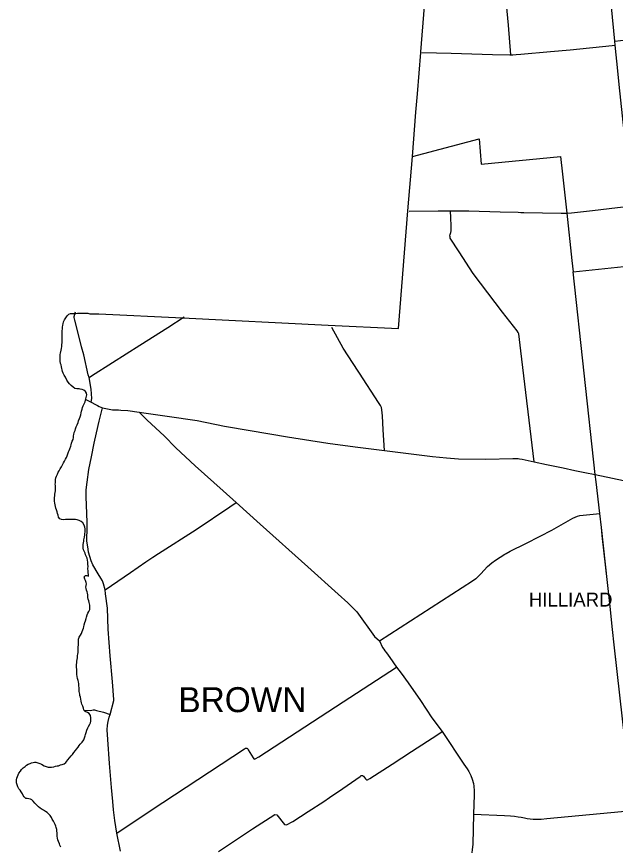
# Model space of a CAD drawing. Extents: x 1755200 to 1902939, y 644115 to 788070.
# Drawn here: x 1755337 to 1776912, y 728043 to 757899 of the extents above; entities that cross this region are included whole.
import ezdxf

# ---------------------------------------------------------------- set-up
doc = ezdxf.new("R2010")
doc.units = 0
for name, color, linetype in [('GM_X_City_Street', 7, 'Continuous'), ('GM_X_Corporation_Text', 7, 'Continuous'), ('GM_X_County', 7, 'Continuous'), ('GM_X_County_Road', 7, 'Continuous'), ('GM_X_Township', 7, 'Continuous'), ('GM_X_Township_Road', 7, 'Continuous'), ('GM_X_Township_Text', 7, 'Continuous')]:
    doc.layers.add(name, color=color, linetype=linetype)

msp = doc.modelspace()

# ---------------------------------------------------------------- linework, layer by layer
at = {"layer": 'GM_X_City_Street'}
for points in [[(1776894, 757007), (1776536, 760730), (1776379, 762498), (1776312, 763238), (1776297, 763289)], [(1773148, 756519), (1773062, 757592), (1772919, 759113), (1772768, 760711), (1772766, 760732)], [(1773219, 756522), (1773341, 756531), (1773503, 756545), (1774575, 756635), (1775276, 756706), (1776795, 756852), (1776906, 756865)], [(1776906, 756865), (1776894, 757007)], [(1777229, 753738), (1777227, 753759), (1777049, 755454), (1776999, 755942), (1776906, 756865)], [(1775031, 741641), (1775451, 741553), (1775814, 741476), (1776185, 741398)], [(1776185, 741398), (1777436, 741136), (1777570, 741122), (1777965, 741145), (1778532, 741169)], [(1776628, 737517), (1776438, 739206)], [(1771881, 737657), (1771905, 737673), (1771965, 737732), (1772058, 737823), (1772302, 738085), (1772460, 738225), (1772594, 738317), (1772932, 738534), (1772978, 738561)], [(1776955, 734518), (1776883, 735163), (1776797, 735932), (1776733, 736538), (1776628, 737517)]]:
    msp.add_lwpolyline(points, dxfattribs=at)
at = {"layer": 'GM_X_County'}
msp.add_lwpolyline([(1756928, 727976), (1756901, 728049), (1756878, 728103), (1756853, 728180), (1756828, 728247), (1756811, 728307), (1756800, 728376), (1756797, 728448), (1756794, 728500), (1756789, 728562), (1756782, 728621), (1756769, 728687), (1756753, 728740), (1756730, 728792), (1756703, 728845), (1756664, 728912), (1756625, 728986), (1756590, 729049), (1756543, 729120), (1756501, 729171), (1756444, 729230), (1756378, 729267), (1756309, 729314), (1756259, 729336), (1756191, 729379), (1756132, 729429), (1756066, 729496), (1755999, 729569), (1755939, 729636), (1755888, 729685), (1755836, 729710), (1755778, 729724), (1755721, 729731), (1755667, 729739), (1755612, 729792), (1755578, 729843), (1755547, 729897), (1755499, 729976), (1755462, 730037), (1755424, 730087), (1755381, 730154), (1755353, 730223), (1755338, 730295), (1755337, 730349), (1755339, 730401), (1755350, 730471), (1755369, 730523), (1755396, 730591), (1755424, 730643), (1755473, 730717), (1755516, 730773), (1755571, 730836), (1755642, 730890), (1755695, 730932), (1755749, 730967), (1755824, 730998), (1755877, 731016), (1755931, 731033), (1755985, 731037), (1756035, 731036), (1756100, 731022), (1756172, 730997), (1756238, 730964), (1756327, 730913), (1756397, 730884), (1756473, 730863), (1756538, 730858), (1756594, 730864), (1756674, 730879), (1756741, 730892), (1756797, 730904), (1756852, 730915), (1756922, 730941), (1756977, 730960), (1757047, 730984), (1757110, 731027), (1757187, 731123), (1757244, 731194), (1757299, 731264), (1757350, 731314), (1757405, 731389), (1757462, 731459), (1757501, 731515), (1757550, 731578), (1757597, 731644), (1757630, 731696), (1757697, 731766), (1757754, 731851), (1757785, 731917), (1757810, 731985), (1757820, 732041), (1757839, 732111), (1757864, 732189), (1757899, 732277), (1757926, 732329), (1757975, 732405), (1757996, 732457), (1758009, 732515), (1758013, 732571), (1758010, 732644), (1757995, 732722), (1757953, 732791), (1757890, 732829), (1757808, 732864), (1757775, 732906), (1757762, 732921), (1757743, 732992), (1757719, 733060), (1757690, 733133), (1757677, 733185), (1757665, 733235), (1757648, 733306), (1757635, 733378), (1757621, 733443), (1757612, 733493), (1757604, 733543), (1757597, 733593), (1757592, 733662), (1757588, 733716), (1757583, 733796), (1757578, 733869), (1757567, 733935), (1757551, 733985), (1757536, 734056), (1757523, 734124), (1757513, 734204), (1757510, 734255), (1757507, 734329), (1757504, 734387), (1757500, 734451), (1757499, 734508), (1757501, 734562), (1757508, 734624), (1757513, 734676), (1757518, 734738), (1757526, 734805), (1757537, 734879), (1757546, 734935), (1757552, 734989), (1757559, 735065), (1757558, 735135), (1757559, 735202), (1757564, 735262), (1757564, 735312), (1757567, 735362), (1757569, 735416), (1757572, 735470), (1757593, 735549), (1757636, 735612), (1757675, 735678), (1757702, 735744), (1757729, 735812), (1757743, 735868), (1757760, 735918), (1757777, 735988), (1757798, 736072), (1757814, 736128), (1757840, 736216), (1757852, 736266), (1757883, 736350), (1757910, 736404), (1757941, 736468), (1757974, 736544), (1757982, 736594), (1757981, 736646), (1757976, 736697), (1757964, 736747), (1757949, 736797), (1757935, 736848), (1757920, 736910), (1757910, 736970), (1757903, 737023), (1757900, 737075), (1757892, 737127), (1757881, 737177), (1757859, 737240), (1757840, 737294), (1757832, 737349), (1757843, 737401), (1757852, 737467), (1757848, 737517), (1757823, 737586), (1757795, 737636), (1757776, 737713), (1757819, 737768), (1757869, 737762), (1757927, 737747), (1757924, 737801), (1757920, 737864), (1757917, 737928), (1757910, 738000), (1757911, 738105), (1757910, 738161), (1757907, 738243), (1757898, 738320), (1757876, 738392), (1757847, 738461), (1757825, 738511), (1757802, 738567), (1757769, 738638), (1757753, 738690), (1757738, 738749), (1757730, 738819), (1757733, 738883), (1757744, 738941), (1757754, 738999), (1757763, 739055), (1757780, 739149), (1757793, 739228), (1757796, 739275), (1757805, 739328), (1757807, 739385), (1757802, 739441), (1757792, 739507), (1757771, 739577), (1757718, 739662), (1757666, 739707), (1757596, 739752), (1757522, 739775), (1757454, 739786), (1757376, 739788), (1757326, 739785), (1757257, 739786), (1757183, 739788), (1757105, 739777), (1757028, 739775), (1756961, 739782), (1756892, 739804), (1756849, 739866), (1756835, 739937), (1756814, 740001), (1756799, 740059), (1756775, 740130), (1756752, 740194), (1756738, 740255), (1756729, 740311), (1756718, 740377), (1756709, 740446), (1756707, 740500), (1756708, 740578), (1756715, 740638), (1756721, 740697), (1756728, 740753), (1756735, 740815), (1756736, 740931), (1756735, 741002), (1756733, 741054), (1756734, 741104), (1756737, 741162), (1756743, 741220), (1756756, 741280), (1756781, 741342), (1756812, 741410), (1756841, 741482), (1756872, 741536), (1756908, 741608), (1756952, 741684), (1756988, 741756), (1757033, 741827), (1757068, 741887), (1757101, 741955), (1757130, 742019), (1757159, 742071), (1757188, 742145), (1757211, 742215), (1757233, 742267), (1757256, 742329), (1757287, 742419), (1757302, 742471), (1757319, 742537), (1757344, 742603), (1757374, 742669), (1757385, 742733), (1757392, 742793), (1757403, 742849), (1757415, 742918), (1757442, 742992), (1757455, 743046), (1757484, 743118), (1757521, 743193), (1757554, 743273), (1757573, 743333), (1757600, 743415), (1757625, 743485), (1757646, 743551), (1757667, 743628), (1757679, 743684), (1757698, 743754), (1757715, 743822), (1757734, 743880), (1757767, 743946), (1757808, 744022), (1757835, 744132), (1757871, 744270), (1757861, 744330), (1757822, 744393), (1757754, 744446), (1757694, 744466), (1757626, 744483), (1757587, 744493), (1757506, 744494), (1757437, 744503), (1757372, 744544), (1757304, 744605), (1757247, 744668), (1757199, 744735), (1757148, 744805), (1757095, 744914), (1757053, 744987), (1757018, 745058), (1756996, 745108), (1756981, 745169), (1756970, 745223), (1756954, 745283), (1756939, 745352), (1756924, 745406), (1756912, 745482), (1756909, 745539), (1756908, 745589), (1756906, 745655), (1756911, 745721), (1756916, 745772), (1756941, 745884), (1756952, 745940), (1756965, 746016), (1756971, 746088), (1756978, 746150), (1756981, 746205), (1756982, 746345), (1756981, 746423), (1756980, 746476), (1756981, 746540), (1756983, 746592), (1756988, 746642), (1756993, 746714), (1757001, 746777), (1757016, 746835), (1757031, 746905), (1757060, 746975), (1757113, 747048), (1757160, 747116), (1757225, 747180), (1757275, 747199), (1757344, 747205), (1757414, 747206), (1757460, 747207), (1757473, 747208), (1757535, 747211), (1757605, 747212), (1757659, 747213), (1757732, 747215), (1757788, 747214), (1757850, 747219), (1757904, 747215), (1757976, 747196), (1758041, 747195), (1758111, 747190), (1758167, 747194), (1758245, 747197), (1758300, 747197), (1761315, 747047), (1766565, 746786), (1769094, 746660), (1769438, 750907), (1769596, 752863), (1769725, 754457), (1769778, 755119), (1769899, 756607), (1769900, 756629), (1770794, 767696)], dxfattribs=at)
at = {"layer": 'GM_X_County_Road'}
for points in [[(1776894, 757007), (1777705, 757105), (1778018, 757141), (1778128, 757155), (1778233, 757166), (1778365, 757180), (1778492, 757194), (1778619, 757207), (1778747, 757219), (1778884, 757232), (1779113, 757254)], [(1769936, 756607), (1770994, 756577), (1772483, 756531), (1773109, 756515), (1773148, 756519), (1773180, 756519), (1773219, 756522)], [(1769475, 750893), (1770527, 750905), (1770648, 750903)], [(1770648, 750903), (1770967, 750899), (1771020, 750898)], [(1773983, 741863), (1773506, 745854), (1773426, 746473), (1773411, 746517), (1773372, 746576), (1772842, 747254), (1771788, 748648), (1771288, 749424), (1770963, 749917), (1770952, 749960), (1770951, 749998), (1770960, 750048), (1770983, 750116), (1770995, 750178), (1770994, 750363), (1770979, 750652), (1770967, 750899)], [(1771020, 750898), (1771633, 750897), (1772757, 750868), (1773413, 750848), (1773509, 750846)], [(1775150, 750817), (1775158, 750818), (1775331, 750827), (1776081, 750915), (1776992, 751020), (1777501, 751079)], [(1773509, 750846), (1773532, 750846), (1773615, 750844)], [(1773615, 750844), (1774956, 750814), (1775150, 750817)], [(1758028, 744012), (1758051, 744141), (1758027, 744481), (1757947, 744901), (1758032, 744953), (1758790, 745444), (1759781, 746058), (1760787, 746701), (1761374, 747087)], [(1757811, 744117), (1758028, 744012), (1758184, 743922), (1758249, 743885), (1758311, 743857), (1758432, 743811), (1758790, 743739), (1759009, 743729)], [(1759078, 727831), (1758945, 728479), (1758873, 728938), (1758824, 729324), (1758805, 729621), (1758759, 730125), (1758686, 730990), (1758621, 731860), (1758606, 732209), (1758617, 732378), (1758635, 732508), (1758678, 732664), (1758706, 732763), (1758836, 733266), (1758838, 733298), (1758793, 733934), (1758710, 734869), (1758639, 735828), (1758612, 736588), (1758545, 737105), (1758527, 737255), (1758468, 737461), (1758428, 737568), (1758371, 737675), (1758280, 737820), (1758085, 738146), (1758026, 738294), (1757930, 738604), (1757913, 738712), (1757870, 739011), (1757885, 739507), (1757884, 739675), (1757871, 740002), (1757847, 740604), (1757846, 740857), (1757877, 741132), (1757941, 741581), (1758033, 742046), (1758138, 742529), (1758216, 742904), (1758310, 743319), (1758432, 743811)], [(1759009, 743729), (1759094, 743725), (1759344, 743705), (1759750, 743647), (1760757, 743508), (1761841, 743352), (1762831, 743141), (1763747, 742984), (1765092, 742758), (1766553, 742527), (1767540, 742406), (1768597, 742273), (1770323, 742056), (1770821, 742006), (1771263, 741969), (1772237, 741956), (1773210, 741980), (1773404, 741976), (1773460, 741972), (1773557, 741957), (1773983, 741863), (1774429, 741768), (1775031, 741641)], [(1759750, 743647), (1760037, 743365), (1760657, 742794), (1761076, 742359), (1761776, 741715), (1762778, 740818), (1763249, 740393), (1764112, 739615), (1765830, 738074), (1766924, 737096), (1767268, 736782), (1767553, 736510), (1767597, 736458), (1768235, 735572), (1768414, 735412), (1768518, 735177), (1768564, 735114), (1768609, 735051), (1768660, 734981), (1768779, 734817), (1769022, 734465), (1769025, 734460), (1769196, 734250), (1769443, 733904), (1769892, 733259), (1770302, 732643), (1770672, 732147), (1771453, 730972), (1771572, 730796)], [(1776438, 739206), (1776406, 739489), (1776347, 739997), (1776216, 741134), (1776185, 741398)], [(1772978, 738561), (1773120, 738644), (1773682, 738923), (1774202, 739185), (1774621, 739399), (1775376, 739831), (1775549, 739905), (1775634, 739927), (1776347, 739997)], [(1768414, 735412), (1771761, 737577), (1771881, 737657)], [(1758945, 728479), (1760187, 729315), (1763552, 731527), (1763588, 731545), (1763614, 731547), (1763634, 731543), (1763654, 731530), (1763686, 731492), (1763858, 731198), (1763880, 731164), (1763900, 731154), (1763930, 731158), (1764061, 731237), (1767098, 733220), (1769022, 734465)], [(1757764, 732920), (1757998, 732905), (1758102, 732921), (1758148, 732927), (1758216, 732908), (1758474, 732842), (1758706, 732763)], [(1771572, 730796), (1771630, 730709), (1771707, 730556), (1771756, 730433), (1771794, 730279), (1771811, 730181), (1771820, 730005), (1771820, 729866), (1771794, 729168)], [(1771794, 729168), (1771770, 728090), (1771716, 727585), (1771714, 727532)], [(1771794, 729168), (1772912, 729117), (1773134, 729105), (1773270, 729095), (1773412, 729078), (1773515, 729060), (1773633, 729037), (1773733, 729018), (1773839, 729000), (1773954, 728991), (1774076, 728987), (1774241, 728991), (1774436, 729008), (1777513, 729300)]]:
    msp.add_lwpolyline(points, dxfattribs=at)
at = {"layer": 'GM_X_Township'}
for points in [[(1769596, 752863), (1772003, 753500), (1772077, 752586), (1774938, 752864), (1775007, 752225), (1775158, 750818), (1775343, 749117), (1775388, 748700)], [(1777437, 730152), (1776883, 735163), (1776797, 735932), (1776733, 736538), (1776628, 737517), (1776406, 739489), (1776347, 739997), (1776216, 741134), (1776185, 741398), (1775388, 748700), (1777665, 748948)]]:
    msp.add_lwpolyline(points, dxfattribs=at)
at = {"layer": 'GM_X_Township_Road'}
for points in [[(1757947, 744901), (1757916, 744999), (1757764, 745715), (1757670, 746003), (1757556, 746495), (1757434, 746957), (1757414, 747057), (1757416, 747097), (1757457, 747263)], [(1768597, 742273), (1768544, 743007), (1768514, 743515), (1768500, 743732), (1768481, 743820), (1768449, 743894), (1768377, 743995), (1767686, 745056), (1767642, 745122), (1767104, 745954), (1766691, 746701)], [(1758527, 737255), (1759437, 737876), (1759994, 738256), (1760240, 738427), (1760444, 738561), (1761804, 739424), (1763025, 740244), (1763249, 740393)], [(1762606, 727820), (1763836, 728646), (1764644, 729158), (1764710, 729140), (1764984, 728802), (1765066, 728782), (1765289, 728907), (1765843, 729261), (1766408, 729626), (1766610, 729764), (1767092, 730091), (1767718, 730527), (1767756, 730558), (1767784, 730562), (1767804, 730558), (1767832, 730542), (1767905, 730439), (1767939, 730403), (1767955, 730403), (1767983, 730403), (1768064, 730450), (1768868, 730975), (1769564, 731426), (1770512, 732036), (1770672, 732147)]]:
    msp.add_lwpolyline(points, dxfattribs=at)

# ---------------------------------------------------------------- texts
at = {"layer": 'GM_X_Corporation_Text'}
msp.add_text('HILLIARD', height=500, rotation=0, dxfattribs=at).set_placement((1773795, 736647))
at = {"layer": 'GM_X_Township_Text'}
msp.add_text('BROWN', height=900, rotation=0, dxfattribs=at).set_placement((1761166, 732843))

doc.saveas('drawing.dxf')
